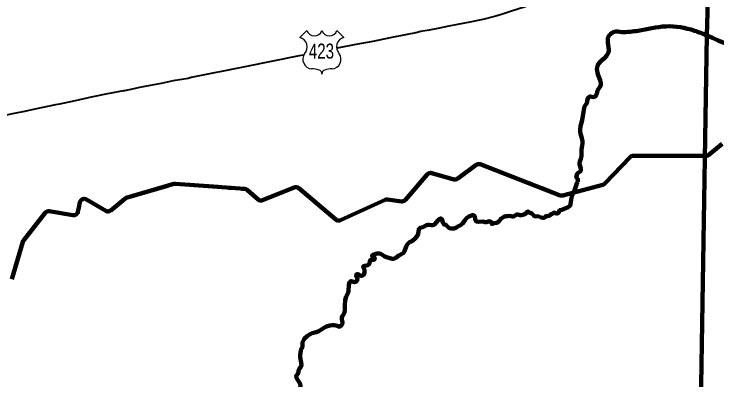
# Model space of a CAD drawing. Extents: x 553962 to 842807, y 8883888 to 9032388.
# Drawn here: x 621164 to 637499, y 8964968 to 8973471 of the extents above; entities that cross this region are included whole.
import ezdxf
from ezdxf.enums import TextEntityAlignment as Align

# ---------------------------------------------------------------- set-up
doc = ezdxf.new("R2010")
doc.units = 0
doc.header["$LTSCALE"] = 200
doc.linetypes.add('DOT_DASHED', pattern=[7.7, 5, -1.2, 0.3, -1.2])
for name, color, linetype, lineweight in [('12', 7, 'Continuous', 25), ('24', 7, 'Continuous', 25), ('48', 7, 'Continuous', 25), ('7', 7, 'Continuous', 90), ('9', 7, 'Continuous', 90)]:
    doc.layers.add(name, color=color, linetype=linetype, lineweight=lineweight)

msp = doc.modelspace()

# ---------------------------------------------------------------- linework, layer by layer
at = {"layer": '12', "lineweight": 40}
for points in [[(636526.5, 8974783.6), (636082.7, 8974635.6), (635662.2, 8974501.7), (635260.8, 8974371.9), (634884.1, 8974246.1), (634508.7, 8974119.3), (634143, 8973999.6), (633777.1, 8973878.8), (633411.3, 8973759), (633045.5, 8973640.3), (632701.6, 8973531.6), (632515, 8973468.2), (632359.8, 8973423.8), (632056.8, 8973345.2), (631756.7, 8973285.7), (631470.2, 8973228.1), (631226.1, 8973179.7), (631010.7, 8973135.2), (630810.4, 8973099.9), (630618.3, 8973063.5), (630498.6, 8973037.3), (630299.5, 8972998.9)], [(630299.5, 8972998.9), (629900.9, 8972917.2), (629502.3, 8972835.4), (629106.4, 8972761.7), (628714.6, 8972683.9), (628658.2, 8972671.9)], [(627892.1, 8972517.3), (627787.3, 8972497.2), (626527.3, 8972247.8), (625278.3, 8971995.4), (625208.3, 8971975.3), (624859.1, 8971919.6), (624586.2, 8971856.1), (624327.1, 8971807.6), (624078.9, 8971766.2), (623877.2, 8971718.8), (623688.2, 8971682.4)], [(623749, 8971693.5), (623336.6, 8971616.7), (622957.2, 8971536), (622583.2, 8971453.3), (622220.1, 8971379.6), (622127, 8971357.4)], [(622127, 8971357.4), (621646.3, 8971257.5), (621405.3, 8971207.1)], [(621405.3, 8971207.1), (621164.3, 8971156.6), (620679.5, 8971055.7), (620194.7, 8970957.7), (619622.5, 8970843.7), (619047.4, 8970728.6), (618626.9, 8970634.8), (618210.5, 8970553), (617794.1, 8970471.2), (617379.1, 8970389.4), (616970.9, 8970302.6), (616723.1, 8970254.2)]]:
    msp.add_lwpolyline(points, dxfattribs=at)
at = {"layer": '24'}
for points in [[(635289.1, 8973046.9), (635193.3, 8973064.8), (635152.3, 8973065.7), (635121.8, 8973060.6), (635088.4, 8973049.6), (635061.3, 8973033.5), (635024.5, 8973002.4), (634997.2, 8972972.3), (634966.1, 8972918.2), (634961, 8972900.1), (634963.3, 8972809), (634982.5, 8972700.9), (634988.3, 8972634.8), (634977.1, 8972576.7), (634957, 8972536.6), (634931, 8972498.5), (634893.6, 8972457.3), (634810.8, 8972383.1), (634757.5, 8972324.9), (634734.8, 8972291.8), (634721.1, 8972258.8), (634713.2, 8972225.7), (634711, 8972195.6), (634723.7, 8972103.5), (634738.5, 8972051.5), (634787.3, 8971934.3), (634802.1, 8971867.3), (634801, 8971826.2), (634787, 8971787.1), (634735.3, 8971720.9), (634725.3, 8971693.9), (634707.4, 8971613.7), (634694.8, 8971588.7), (634670.6, 8971557.6), (634653, 8971546.5), (634625.3, 8971541.5), (634559.7, 8971552.4), (634539.5, 8971553.4), (634505.6, 8971527.3), (634489.3, 8971482.2), (634473.5, 8971402), (634424.6, 8971322.8), (634411, 8971288.8), (634363.8, 8971005.2), (634331.5, 8970867), (634319.9, 8970779.8), (634321.1, 8970743.8), (634328.9, 8970692.7), (634361.6, 8970589.6), (634374.7, 8970513.5), (634371.4, 8970461.4), (634350, 8970323.2), (634349.1, 8970169.9), (634336.1, 8970107.8), (634312.2, 8970046.7), (634303.6, 8970002.6), (634304.6, 8969985.6), (634333.8, 8969882.4), (634332.9, 8969828.3), (634324.3, 8969808.3), (634272.2, 8969782.2), (634248.5, 8969757.1), (634230.1, 8969676), (634268.6, 8969630), (634268.6, 8969569.3)], [(634268.6, 8969569.3), (634244.3, 8969539), (634226.1, 8969484.3), (634214, 8969441.9), (634171.5, 8969332.7), (634116.8, 8969205.3), (634098.6, 8969053.6), (634086.5, 8969017.2), (634039.3, 8968984.8)], [(634039.3, 8968984.8), (633892.2, 8968920.1), (633841.2, 8968911.2), (633829, 8968894.2), (633826.5, 8968860.1), (633814.7, 8968848.1), (633792.7, 8968839.1), (633772.6, 8968838), (633707.3, 8968856), (633679.2, 8968828.9), (633643, 8968822.8), (633597.4, 8968783.7), (633572.7, 8968776.6), (633532.2, 8968781.6), (633506.6, 8968748.5), (633477, 8968733.4), (633461.8, 8968732.4), (633415.1, 8968740.3), (633342.3, 8968771.2), (633285, 8968769.1), (633251.4, 8968778.1), (633194.6, 8968839.1), (633136, 8968858.1), (633110.7, 8968880), (633099.8, 8968882), (633077.7, 8968869), (633061.8, 8968841.9), (633034, 8968818.8), (632961, 8968800.7), (632917, 8968797.6), (632873.8, 8968812.6), (632857.7, 8968813.5), (632829.5, 8968806.5), (632784.3, 8968774.4), (632762.5, 8968768.3), (632743.5, 8968767.3), (632689.7, 8968778.2), (632635, 8968777.1), (632594.3, 8968772.1), (632546, 8968759), (632474, 8968715.8), (632441.1, 8968661.6), (632402.4, 8968626.5), (632375.7, 8968616.5), (632320, 8968608.4), (632276, 8968592.3), (632267.3, 8968594.3), (632260.3, 8968604.3), (632251.7, 8968645.3), (632234.7, 8968652.3), (632204.8, 8968654.2), (632145, 8968637.1), (632109, 8968631.1), (632058.6, 8968648), (631959.9, 8968641.8), (631914.2, 8968649.8), (631895.5, 8968662.8), (631887.1, 8968674.8), (631878, 8968708.8), (631869.8, 8968767.9), (631863.3, 8968783.9), (631842.8, 8968796.9), (631814.7, 8968800.9), (631735.7, 8968766.7), (631677.1, 8968724.5), (631636.5, 8968676.4), (631586.8, 8968606.2)], [(631586.8, 8968606.2), (631586.8, 8968606.2), (631566, 8968583.1), (631538.7, 8968561.1), (631495.2, 8968543), (631432.7, 8968503.8), (631386.3, 8968486.7), (631328.7, 8968484.6), (631284.8, 8968496.6), (631269.3, 8968505.5), (631202.2, 8968575.6), (631191.8, 8968578.5), (631168.3, 8968573.5), (631157.2, 8968578.5), (631126.3, 8968623.5), (631111.8, 8968681.6), (631101.9, 8968706.6), (631091.9, 8968716.6), (631075.5, 8968722.6), (631055.8, 8968713.5), (631019.8, 8968680.4), (630944.5, 8968589.2), (630924.7, 8968575.1), (630898.9, 8968567.1), (630870.7, 8968563), (630810.1, 8968573.9), (630771.4, 8968571.9), (630733.8, 8968558.8), (630662, 8968521.6), (630604.2, 8968505.5), (630582.5, 8968486.4), (630570.5, 8968464.4), (630552, 8968360.2), (630538.6, 8968328.1), (630519, 8968295), (630475.5, 8968245.9), (630400.9, 8968188.7), (630373.3, 8968178.6), (630353.6, 8968166.6), (630308.6, 8968122.4), (630276.4, 8968071.3), (630238.3, 8967960.1), (630219.6, 8967931), (630204, 8967915.9), (630110, 8967856.7), (630037.7, 8967805.5), (630008, 8967791.4), (629973.1, 8967784.4), (629952.7, 8967785.3), (629818.6, 8967822.2), (629765.8, 8967848.1), (629713, 8967885.1), (629664.5, 8967904.1), (629633.8, 8967907), (629598, 8967904), (629531.5, 8967879.8), (629496.2, 8967871.8), (629483.7, 8967859.7), (629486.2, 8967847.7), (629492.6, 8967840.7), (629540.7, 8967810.7), (629545.3, 8967784.7), (629540.8, 8967768.7), (629532.8, 8967760.6), (629522.4, 8967757.6), (629462.2, 8967760.5), (629444.6, 8967756.5), (629432.2, 8967733.4), (629423.8, 8967670.3), (629408.2, 8967648.3), (629382.3, 8967632.2), (629313.2, 8967622.1), (629285.3, 8967611), (629277.8, 8967603), (629278.1, 8967588), (629305.3, 8967533.9), (629310.7, 8967502.9), (629308.8, 8967461.8), (629293.1, 8967414.7), (629266.5, 8967393.6), (629234, 8967384.6), (629199.3, 8967395.5), (629158.3, 8967424.5), (629139.8, 8967426.5), (629123.2, 8967422.5), (629117.6, 8967414.4), (629118, 8967394.4), (629139.5, 8967343.4), (629144.7, 8967309.3), (629140.5, 8967289.3), (629122.5, 8967256.2), (629103.3, 8967245.2), (629075.3, 8967238.1), (629026.3, 8967257.1), (628994.8, 8967264), (628978.7, 8967255), (628957.3, 8967232.9), (628940.9, 8967175.8), (628937.1, 8967045.6), (628928.9, 8966993.5), (628879.5, 8966907.3)], [(628879.5, 8966907.3), (628856.2, 8966825.1), (628856.2, 8966825.1), (628847.9, 8966696.9), (628850.9, 8966584.7), (628846.8, 8966548.7), (628833.2, 8966513.6), (628795.6, 8966457.4), (628777.8, 8966417.3), (628777.8, 8966370.3), (628794.8, 8966312.2), (628795, 8966279.2), (628772.4, 8966240.1), (628724.9, 8966202.9), (628672.1, 8966222.8)], [(628672.1, 8966222.8), (628644.5, 8966231.7), (628607, 8966237.7), (628560.1, 8966237.6), (628499.1, 8966232.5), (628424.4, 8966210.3), (628380.7, 8966187.2), (628295.1, 8966129), (628244.3, 8966100.9), (628182.1, 8966074.8), (628126, 8966063.7), (628091.9, 8966052.6), (628032.2, 8966021.4), (627977.3, 8965986.3), (627925.1, 8965941.1), (627901.8, 8965910.1), (627866.5, 8965837.9), (627864.4, 8965796.7)], [(627864.4, 8965796.7), (627870.8, 8965773.8), (627867.2, 8965732.7), (627839, 8965684.6), (627827.1, 8965654.5), (627811.8, 8965541.3), (627811.5, 8965505.3), (627817.4, 8965449.2), (627838.1, 8965372.1), (627841, 8965321), (627826.7, 8965271.9), (627798.1, 8965236.8), (627783.4, 8965207.8), (627766.8, 8965123.6), (627733.2, 8965082.5), (627726.4, 8965067.5), (627723.3, 8965046.4), (627728.3, 8965015.4), (627739.7, 8964986.4), (627792.5, 8964916.3), (627811.7, 8964876.3), (627823.6, 8964830.2), (627816, 8964796.2)]]:
    msp.add_lwpolyline(points, dxfattribs=at)
at = {"layer": '48'}
for p, q in [((627808.4, 8972926.9), (627968.3, 8973086.8)), ((628667.7, 8973086.8), (628827.6, 8972926.9))]:
    msp.add_line(p, q, dxfattribs=at)
for centre, radius, start, end in [((628143.2, 8973153.7), 187.2, 200.95927, 339.04073), ((628492.8, 8973153.7), 187.2, 200.95927, 339.04073), ((627746.3, 8972705), 230.3, 317.5721, 74.36886), ((628889.7, 8972705), 230.3, 105.62774, 222.4279), ((628099.8, 8972419.9), 224.7, 144.73733, 264.65778), ((628536.2, 8972419.9), 224.7, 275.34222, 35.26267), ((628077.9, 8971606.4), 589.7, 72.89371, 89.90057), ((628223.6, 8972079.8), 94.4, 357.69345, 72.92955), ((628412.4, 8972079.8), 94.4, 107.07045, 182.30655), ((628558.1, 8971606.4), 589.7, 90.09943, 107.10629)]:
    msp.add_arc(centre, radius, start, end, dxfattribs=at)
at = {"layer": '7'}
for points in [[(631406.8, 8969626), (631426.8, 8969626.5), (631446.2, 8969631), (631464.4, 8969639.2), (631474.3, 8969645.8), (631899.6, 8969965.8), (631916.7, 8969976.1), (631935.5, 8969982.9), (631955.3, 8969985.8), (631975.2, 8969984.7), (631994.6, 8969979.6), (631996, 8969979.1), (633854.9, 8969257.5), (633874.2, 8969252.1), (633894.1, 8969250.7), (633913.9, 8969253.3), (633917.1, 8969254.1), (634844.4, 8969503.6), (634863.1, 8969510.7), (634880, 8969521.3), (634890.6, 8969531), (635479.7, 8970145.9), (635494.9, 8970158.9), (635512.4, 8970168.6), (635531.4, 8970174.6), (635551.3, 8970176.7), (635551.9, 8970176.7), (637246.5, 8970176.7), (637266.4, 8970178.7), (637285.5, 8970184.6), (637303, 8970194.2), (637309.8, 8970199.3), (637622.9, 8970455.1)], [(621111.5, 8967313.7), (621371.1, 8968179.3), (621378.9, 8968198.4), (621389.2, 8968214.2), (621888, 8968850.9), (621901.9, 8968865.3), (621918.3, 8968876.7), (621936.6, 8968884.6), (621956.2, 8968888.7), (621976.2, 8968888.8), (621983, 8968887.9), (622532.9, 8968797.4), (622552.8, 8968796.1), (622572.6, 8968798.8), (622591.4, 8968805.5), (622608.6, 8968815.7), (622623.4, 8968829.1), (622635.2, 8968845.2), (622643.6, 8968863.3), (622646.7, 8968874.4), (622669.6, 8968977.3), (622696.2, 8969097.2), (622702.5, 8969116.1), (622712.4, 8969133.5), (622725.5, 8969148.5), (622741.4, 8969160.6), (622759.4, 8969169.4), (622778.7, 8969174.3), (622798.7, 8969175.4), (622818.4, 8969172.4), (622837.2, 8969165.6), (622844.3, 8969161.8), (623294.8, 8968898.1), (623313, 8968889.8), (623332.5, 8968885.3), (623352.4, 8968884.7), (623372.1, 8968888.1), (623390.7, 8968895.3), (623407.5, 8968906.1), (623409.5, 8968907.7), (623735, 8969179.8), (623751.6, 8969191), (623770, 8969198.7), (623770.9, 8969199), (624874.5, 8969523.5), (624895, 8969527.5), (624913.6, 8969527.7), (626527.1, 8969406.8), (626546.8, 8969403.3), (626565.4, 8969396), (626582.2, 8969385.1), (626585.8, 8969382), (626836.8, 8969160.5), (626853.1, 8969148.9), (626871.3, 8969140.7), (626890.8, 8969136.3), (626910.7, 8969135.8), (626930.4, 8969139.3), (626940.7, 8969142.9), (627676.5, 8969442), (627695.6, 8969447.7), (627715.5, 8969449.4), (627735.4, 8969447.1), (627754.4, 8969440.9), (627771.8, 8969431.1), (627778.6, 8969425.8), (628643.2, 8968696.2), (628659.7, 8968684.9), (628678.1, 8968677.1), (628697.7, 8968673.1), (628717.6, 8968673.1), (628737.2, 8968677.1), (628748.9, 8968681.5), (629274.7, 8968919), (629788.6, 8969151.2), (629807.5, 8969157.6), (629827.3, 8969160), (629842.6, 8969159.2), (630170.1, 8969116.9), (630190.1, 8969116.4), (630209.8, 8969119.8), (630228.4, 8969127), (630245.2, 8969137.8), (630258.8, 8969151), (630767.5, 8969743.7), (630782, 8969757.5), (630798.9, 8969768.1), (630817.6, 8969775.2), (630837.3, 8969778.4), (630857.3, 8969777.6), (630870.5, 8969774.8), (631387.1, 8969629.5), (631406.8, 8969626)]]:
    msp.add_lwpolyline(points, dxfattribs=at)
at = {"layer": '7', "linetype": 'DOT_DASHED'}
for points in [[(631406.8, 8969626), (631426.8, 8969626.5), (631446.2, 8969631), (631464.4, 8969639.2), (631474.3, 8969645.8), (631899.6, 8969965.8), (631916.7, 8969976.1), (631935.5, 8969982.9), (631955.3, 8969985.8), (631975.2, 8969984.7), (631994.6, 8969979.6), (631996, 8969979.1), (633854.9, 8969257.5), (633874.2, 8969252.1), (633894.1, 8969250.7), (633913.9, 8969253.3), (633917.1, 8969254.1), (634844.4, 8969503.6), (634863.1, 8969510.7), (634880, 8969521.3), (634890.6, 8969531), (635479.7, 8970145.9), (635494.9, 8970158.9), (635512.4, 8970168.6), (635531.4, 8970174.6), (635551.3, 8970176.7), (635551.9, 8970176.7), (637246.5, 8970176.7), (637266.4, 8970178.7), (637285.5, 8970184.6), (637303, 8970194.2), (637309.8, 8970199.3), (637622.9, 8970455.1)], [(621111.5, 8967313.7), (621371.1, 8968179.3), (621378.9, 8968198.4), (621389.2, 8968214.2), (621888, 8968850.9), (621901.9, 8968865.3), (621918.3, 8968876.7), (621936.6, 8968884.6), (621956.2, 8968888.7), (621976.2, 8968888.8), (621983, 8968887.9), (622532.9, 8968797.4), (622552.8, 8968796.1), (622572.6, 8968798.8), (622591.4, 8968805.5), (622608.6, 8968815.7), (622623.4, 8968829.1), (622635.2, 8968845.2), (622643.6, 8968863.3), (622646.7, 8968874.4), (622669.6, 8968977.3), (622696.2, 8969097.2), (622702.5, 8969116.1), (622712.4, 8969133.5), (622725.5, 8969148.5), (622741.4, 8969160.6), (622759.4, 8969169.4), (622778.7, 8969174.3), (622798.7, 8969175.4), (622818.4, 8969172.4), (622837.2, 8969165.6), (622844.3, 8969161.8), (623294.8, 8968898.1), (623313, 8968889.8), (623332.5, 8968885.3), (623352.4, 8968884.7), (623372.1, 8968888.1), (623390.7, 8968895.3), (623407.5, 8968906.1), (623409.5, 8968907.7), (623735, 8969179.8), (623751.6, 8969191), (623770, 8969198.7), (623770.9, 8969199), (624874.5, 8969523.5), (624895, 8969527.5), (624913.6, 8969527.7), (626527.1, 8969406.8), (626546.8, 8969403.3), (626565.4, 8969396), (626582.2, 8969385.1), (626585.8, 8969382), (626836.8, 8969160.5), (626853.1, 8969148.9), (626871.3, 8969140.7), (626890.8, 8969136.3), (626910.7, 8969135.8), (626930.4, 8969139.3), (626940.7, 8969142.9), (627676.5, 8969442), (627695.6, 8969447.7), (627715.5, 8969449.4), (627735.4, 8969447.1), (627754.4, 8969440.9), (627771.8, 8969431.1), (627778.6, 8969425.8), (628643.2, 8968696.2), (628659.7, 8968684.9), (628678.1, 8968677.1), (628697.7, 8968673.1), (628717.6, 8968673.1), (628737.2, 8968677.1), (628748.9, 8968681.5), (629274.7, 8968919), (629788.6, 8969151.2), (629807.5, 8969157.6), (629827.3, 8969160), (629842.6, 8969159.2), (630170.1, 8969116.9), (630190.1, 8969116.4), (630209.8, 8969119.8), (630228.4, 8969127), (630245.2, 8969137.8), (630258.8, 8969151), (630767.5, 8969743.7), (630782, 8969757.5), (630798.9, 8969768.1), (630817.6, 8969775.2), (630837.3, 8969778.4), (630857.3, 8969777.6), (630870.5, 8969774.8), (631387.1, 8969629.5), (631406.8, 8969626)]]:
    msp.add_lwpolyline(points, dxfattribs=at)
at = {"layer": '9'}
for points in [[(637260.6, 8972975.8), (637390.8, 8977204.2), (635350.7, 8977923.9), (623791.9, 8983133)], [(635289.1, 8973046.9), (635193.3, 8973064.8), (635152.3, 8973065.7), (635121.8, 8973060.6), (635088.4, 8973049.6), (635061.3, 8973033.5), (635024.5, 8973002.4), (634997.2, 8972972.3), (634966.1, 8972918.2), (634961, 8972900.1), (634963.3, 8972809), (634982.5, 8972700.9), (634988.3, 8972634.8), (634977.1, 8972576.7), (634957, 8972536.6), (634931, 8972498.5), (634893.6, 8972457.3), (634810.8, 8972383.1), (634757.5, 8972324.9), (634734.8, 8972291.8), (634721.1, 8972258.8), (634713.2, 8972225.7), (634711, 8972195.6), (634723.7, 8972103.5), (634738.5, 8972051.5), (634787.3, 8971934.3), (634802.1, 8971867.3), (634801, 8971826.2), (634787, 8971787.1), (634735.3, 8971720.9), (634725.3, 8971693.9), (634707.4, 8971613.7), (634694.8, 8971588.7), (634670.6, 8971557.6), (634653, 8971546.5), (634625.3, 8971541.5), (634559.7, 8971552.4), (634539.5, 8971553.4), (634505.6, 8971527.3), (634489.3, 8971482.2), (634473.5, 8971402), (634424.6, 8971322.8), (634411, 8971288.8), (634363.8, 8971005.2), (634331.5, 8970867), (634319.9, 8970779.8), (634321.1, 8970743.8), (634328.9, 8970692.7), (634361.6, 8970589.6), (634374.7, 8970513.5), (634371.4, 8970461.4), (634350, 8970323.2), (634349.1, 8970169.9), (634336.1, 8970107.8), (634312.2, 8970046.7), (634303.6, 8970002.6), (634304.6, 8969985.6), (634333.8, 8969882.4), (634332.9, 8969828.3), (634324.3, 8969808.3), (634272.2, 8969782.2), (634248.5, 8969757.1), (634230.1, 8969676), (634268.6, 8969630), (634268.6, 8969569.3)], [(637260.6, 8972975.8), (637076.8, 8961505.7), (634855.7, 8958401.3), (634875.3, 8955110.3)], [(634268.6, 8969569.3), (634244.3, 8969539), (634226.1, 8969484.3), (634214, 8969441.9), (634171.5, 8969332.7), (634116.8, 8969205.3), (634098.6, 8969053.6), (634086.5, 8969017.2), (634039.3, 8968984.8)], [(634039.3, 8968984.8), (633892.2, 8968920.1), (633841.2, 8968911.2), (633829, 8968894.2), (633826.5, 8968860.1), (633814.7, 8968848.1), (633792.7, 8968839.1), (633772.6, 8968838), (633707.3, 8968856), (633679.2, 8968828.9), (633643, 8968822.8), (633597.4, 8968783.7), (633572.7, 8968776.6), (633532.2, 8968781.6), (633506.6, 8968748.5), (633477, 8968733.4), (633461.8, 8968732.4), (633415.1, 8968740.3), (633342.3, 8968771.2), (633285, 8968769.1), (633251.4, 8968778.1), (633194.6, 8968839.1), (633136, 8968858.1), (633110.7, 8968880), (633099.8, 8968882), (633077.7, 8968869), (633061.8, 8968841.9), (633034, 8968818.8), (632961, 8968800.7), (632917, 8968797.6), (632873.8, 8968812.6), (632857.7, 8968813.5), (632829.5, 8968806.5), (632784.3, 8968774.4), (632762.5, 8968768.3), (632743.5, 8968767.3), (632689.7, 8968778.2), (632635, 8968777.1), (632594.3, 8968772.1), (632546, 8968759), (632474, 8968715.8), (632441.1, 8968661.6), (632402.4, 8968626.5), (632375.7, 8968616.5), (632320, 8968608.4), (632276, 8968592.3), (632267.3, 8968594.3), (632260.3, 8968604.3), (632251.7, 8968645.3), (632234.7, 8968652.3), (632204.8, 8968654.2), (632145, 8968637.1), (632109, 8968631.1), (632058.6, 8968648), (631959.9, 8968641.8), (631914.2, 8968649.8), (631895.5, 8968662.8), (631887.1, 8968674.8), (631878, 8968708.8), (631869.8, 8968767.9), (631863.3, 8968783.9), (631842.8, 8968796.9), (631814.7, 8968800.9), (631735.7, 8968766.7), (631677.1, 8968724.5), (631636.5, 8968676.4), (631586.8, 8968606.2)], [(631586.8, 8968606.2), (631586.8, 8968606.2), (631566, 8968583.1), (631538.7, 8968561.1), (631495.2, 8968543), (631432.7, 8968503.8), (631386.3, 8968486.7), (631328.7, 8968484.6), (631284.8, 8968496.6), (631269.3, 8968505.5), (631202.2, 8968575.6), (631191.8, 8968578.5), (631168.3, 8968573.5), (631157.2, 8968578.5), (631126.3, 8968623.5), (631111.8, 8968681.6), (631101.9, 8968706.6), (631091.9, 8968716.6), (631075.5, 8968722.6), (631055.8, 8968713.5), (631019.8, 8968680.4), (630944.5, 8968589.2), (630924.7, 8968575.1), (630898.9, 8968567.1), (630870.7, 8968563), (630810.1, 8968573.9), (630771.4, 8968571.9), (630733.8, 8968558.8), (630662, 8968521.6), (630604.2, 8968505.5), (630582.5, 8968486.4), (630570.5, 8968464.4), (630552, 8968360.2), (630538.6, 8968328.1), (630519, 8968295), (630475.5, 8968245.9), (630400.9, 8968188.7), (630373.3, 8968178.6), (630353.6, 8968166.6), (630308.6, 8968122.4), (630276.4, 8968071.3), (630238.3, 8967960.1), (630219.6, 8967931), (630204, 8967915.9), (630110, 8967856.7), (630037.7, 8967805.5), (630008, 8967791.4), (629973.1, 8967784.4), (629952.7, 8967785.3), (629818.6, 8967822.2), (629765.8, 8967848.1), (629713, 8967885.1), (629664.5, 8967904.1), (629633.8, 8967907), (629598, 8967904), (629531.5, 8967879.8), (629496.2, 8967871.8), (629483.7, 8967859.7), (629486.2, 8967847.7), (629492.6, 8967840.7), (629540.7, 8967810.7), (629545.3, 8967784.7), (629540.8, 8967768.7), (629532.8, 8967760.6), (629522.4, 8967757.6), (629462.2, 8967760.5), (629444.6, 8967756.5), (629432.2, 8967733.4), (629423.8, 8967670.3), (629408.2, 8967648.3), (629382.3, 8967632.2), (629313.2, 8967622.1), (629285.3, 8967611), (629277.8, 8967603), (629278.1, 8967588), (629305.3, 8967533.9), (629310.7, 8967502.9), (629308.8, 8967461.8), (629293.1, 8967414.7), (629266.5, 8967393.6), (629234, 8967384.6), (629199.3, 8967395.5), (629158.3, 8967424.5), (629139.8, 8967426.5), (629123.2, 8967422.5), (629117.6, 8967414.4), (629118, 8967394.4), (629139.5, 8967343.4), (629144.7, 8967309.3), (629140.5, 8967289.3), (629122.5, 8967256.2), (629103.3, 8967245.2), (629075.3, 8967238.1), (629026.3, 8967257.1), (628994.8, 8967264), (628978.7, 8967255), (628957.3, 8967232.9), (628940.9, 8967175.8), (628937.1, 8967045.6), (628928.9, 8966993.5), (628879.5, 8966907.3)], [(628879.5, 8966907.3), (628856.2, 8966825.1), (628856.2, 8966825.1), (628847.9, 8966696.9), (628850.9, 8966584.7), (628846.8, 8966548.7), (628833.2, 8966513.6), (628795.6, 8966457.4), (628777.8, 8966417.3), (628777.8, 8966370.3), (628794.8, 8966312.2), (628795, 8966279.2), (628772.4, 8966240.1), (628724.9, 8966202.9), (628672.1, 8966222.8)], [(628672.1, 8966222.8), (628644.5, 8966231.7), (628607, 8966237.7), (628560.1, 8966237.6), (628499.1, 8966232.5), (628424.4, 8966210.3), (628380.7, 8966187.2), (628295.1, 8966129), (628244.3, 8966100.9), (628182.1, 8966074.8), (628126, 8966063.7), (628091.9, 8966052.6), (628032.2, 8966021.4), (627977.3, 8965986.3), (627925.1, 8965941.1), (627901.8, 8965910.1), (627866.5, 8965837.9), (627864.4, 8965796.7)], [(627864.4, 8965796.7), (627870.8, 8965773.8), (627867.2, 8965732.7), (627839, 8965684.6), (627827.1, 8965654.5), (627811.8, 8965541.3), (627811.5, 8965505.3), (627817.4, 8965449.2), (627838.1, 8965372.1), (627841, 8965321), (627826.7, 8965271.9), (627798.1, 8965236.8), (627783.4, 8965207.8), (627766.8, 8965123.6), (627733.2, 8965082.5), (627726.4, 8965067.5), (627723.3, 8965046.4), (627728.3, 8965015.4), (627739.7, 8964986.4), (627792.5, 8964916.3), (627811.7, 8964876.3), (627823.6, 8964830.2), (627816, 8964796.2)]]:
    msp.add_lwpolyline(points, dxfattribs=at)
for points in [[(592698.5, 8977198.4), (599903.5, 8973292.7), (608459.2, 8968138.2), (612674.8, 8965332.6), (616842, 8962096.4), (620005, 8958671.2), (621134, 8957974.7), (621473.4, 8956805.3), (621586.2, 8956597.5)], [(637260.6, 8972975.8), (636979.7, 8973082.7), (636310.5, 8973184.6), (635667.8, 8973082.7), (635289.1, 8973046.9)], [(637260.6, 8972975.8), (641524.5, 8971056.2), (652526.1, 8965412.7), (653164.3, 8965062.8), (670790.5, 8953770.1), (686194, 8943929.9), (696283.3, 8937647.1)]]:
    msp.add_spline(points, degree=3, dxfattribs=at)

# ---------------------------------------------------------------- texts
at = {"layer": '48', "width": 0.75}
msp.add_text('423', height=350, dxfattribs=at).set_placement((628307.7, 8972435.3), align=Align.CENTER)

doc.saveas('drawing.dxf')
